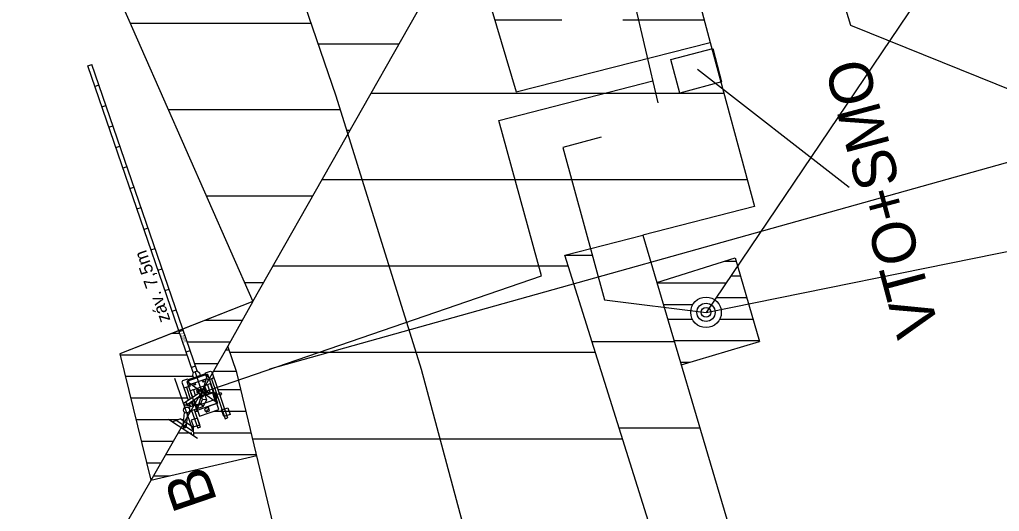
# Model space of a CAD drawing. Extents: x -553916 to -552953, y -1067470 to -1066637.
# Drawn here: x -553520.24 to -553497.58, y -1066994.91 to -1066983.52 of the extents above; entities that cross this region are included whole.
import ezdxf

# ---------------------------------------------------------------- set-up
doc = ezdxf.new("R2010")
doc.units = 0
for name, color, linetype in [('Hranice parcel', 7, 'Continuous'), ('Kolej', 7, 'Continuous'), ('Nová kabelizace', 7, 'Continuous'), ('nové prvky ZZ', 7, 'Continuous'), ('Propustek', 7, 'Continuous'), ('trasa_NN_popisky', 7, 'Continuous'), ('trasa_NN_uzemneni', 7, 'Continuous'), ('Vrstva 1', 7, 'Continuous'), ('Vrstva 28', 7, 'Continuous'), ('Vrstva 58', 7, 'Continuous')]:
    doc.layers.add(name, color=color, linetype=linetype)

msp = doc.modelspace()

# ---------------------------------------------------------------- linework, layer by layer
at = {"layer": 'Hranice parcel'}
for points in [[(-553481.25, -1066991.64), (-553501.02, -1066983.66), (-553503.13, -1066976.7), (-553485.37, -1066948.09)], [(-553515.43, -1066991.08), (-553526.38, -1067010.19), (-553539.65, -1067043.59), (-553548.33, -1067069.03)]]:
    msp.add_lwpolyline(points, dxfattribs=at)
at = {"layer": 'Kolej'}
msp.add_lwpolyline([(-553503.324, -1067065.808), (-553502.678, -1067054.027), (-553502.762, -1067041.504), (-553503.626, -1067029.057), (-553504.756, -1067019.974), (-553506.183, -1067011.388), (-553508.328, -1067001.388), (-553510.948, -1066991.622), (-553512.921, -1066985.291), (-553515.647, -1066977.347), (-553517.422, -1066972.53), (-553519.157, -1066967.95), (-553522.886, -1066958.375), (-553529.101, -1066942.549), (-553538.686, -1066918.107), (-553542.908, -1066907.329), (-553546.692, -1066897.676), (-553555.025, -1066876.441), (-553564.644, -1066851.894), (-553574.241, -1066827.427), (-553583.19, -1066804.618)], dxfattribs=at)
at = {"layer": 'Nová kabelizace'}
for p, q in [((-553505.478, -1066985.448), (-553507.017, -1066978.813)), ((-553509.157, -1066985.86), (-553505.596, -1066984.938)), ((-553508.173, -1066989.45), (-553509.157, -1066985.86)), ((-553516.02, -1066992.15), (-553508.173, -1066989.45))]:
    msp.add_line(p, q, dxfattribs=at)
at = {"layer": 'nové prvky ZZ'}
for p, q in [((-553505.18, -1066984.448), (-553504.213, -1066984.191)), ((-553504.213, -1066984.191), (-553504.008, -1066984.964)), ((-553518.666, -1066984.593), (-553518.572, -1066984.56)), ((-553516.232, -1066991.687), (-553518.666, -1066984.593)), ((-553516.138, -1066991.654), (-553518.572, -1066984.56)), ((-553504.568, -1066984.671), (-553501.059, -1066987.4)), ((-553518.504, -1066985.066), (-553518.41, -1066985.033)), ((-553518.341, -1066985.538), (-553518.248, -1066985.506)), ((-553518.179, -1066986.011), (-553518.085, -1066985.979)), ((-553518.017, -1066986.484), (-553517.923, -1066986.452)), ((-553517.855, -1066986.957), (-553517.761, -1066986.925)), ((-553517.692, -1066987.43), (-553517.598, -1066987.398)), ((-553517.53, -1066987.903), (-553517.436, -1066987.871)), ((-553517.368, -1066988.376), (-553517.274, -1066988.344)), ((-553517.205, -1066988.849), (-553517.112, -1066988.817)), ((-553517.043, -1066989.322), (-553516.949, -1066989.29)), ((-553516.881, -1066989.795), (-553516.787, -1066989.763)), ((-553516.719, -1066990.268), (-553516.625, -1066990.236)), ((-553516.556, -1066990.741), (-553516.462, -1066990.708)), ((-553516.394, -1066991.214), (-553516.3, -1066991.181)), ((-553516.176, -1066991.542), (-553516.27, -1066991.574)), ((-553516.232, -1066991.687), (-553516.138, -1066991.654)), ((-553516.02, -1066992.15), (-553516.185, -1066991.67)), ((-553515.946, -1066991.701), (-553515.827, -1066991.66)), ((-553515.827, -1066991.66), (-553515.798, -1066991.673)), ((-553515.798, -1066991.673), (-553515.432, -1066992.74)), ((-553516.241, -1066993.022), (-553516.65, -1066991.83)), ((-553516.476, -1066991.883), (-553516.491, -1066991.911)), ((-553516.491, -1066991.911), (-553516.348, -1066992.329)), ((-553516.357, -1066991.842), (-553516.476, -1066991.883)), ((-553515.895, -1066991.731), (-553516.377, -1066991.897)), ((-553516.377, -1066991.897), (-553516.145, -1066992.568)), ((-553515.664, -1066992.402), (-553516.377, -1066991.897)), ((-553516.352, -1066991.858), (-553516.357, -1066991.842)), ((-553516.222, -1066991.814), (-553516.065, -1066991.76)), ((-553515.895, -1066991.731), (-553516.145, -1066992.568)), ((-553515.941, -1066991.717), (-553515.946, -1066991.701)), ((-553515.902, -1066991.829), (-553515.891, -1066991.862)), ((-553515.895, -1066991.731), (-553515.664, -1066992.402)), ((-553515.891, -1066991.862), (-553515.772, -1066991.822)), ((-553515.806, -1066991.833), (-553515.488, -1066992.759)), ((-553515.772, -1066991.822), (-553515.757, -1066991.793)), ((-553516.421, -1066992.044), (-553516.45, -1066992.031)), ((-553516.302, -1066992.003), (-553516.421, -1066992.044)), ((-553516.387, -1066992.033), (-553516.297, -1066992.295)), ((-553516.313, -1066991.97), (-553516.302, -1066992.003)), ((-553516.3, -1066992.111), (-553516.23, -1066992.087)), ((-553516.3, -1066992.111), (-553516.248, -1066992.262)), ((-553516.23, -1066992.087), (-553516.228, -1066992.091)), ((-553516.228, -1066992.091), (-553516.224, -1066992.09)), ((-553515.899, -1066991.978), (-553516.224, -1066992.09)), ((-553516.224, -1066992.09), (-553516.18, -1066992.216)), ((-553516.106, -1066992.104), (-553516.125, -1066992.116)), ((-553516.125, -1066992.116), (-553516.111, -1066992.136)), ((-553516.106, -1066992.166), (-553516.113, -1066992.146)), ((-553516.111, -1066992.136), (-553516.093, -1066992.124)), ((-553516.096, -1066992.159), (-553516.102, -1066992.142)), ((-553516.06, -1066992.081), (-553516.095, -1066992.103)), ((-553516.077, -1066992.105), (-553516.089, -1066992.113)), ((-553516.025, -1066992.152), (-553516.015, -1066992.148)), ((-553516.022, -1066992.145), (-553516.019, -1066992.155)), ((-553515.928, -1066992.156), (-553515.951, -1066992.09)), ((-553515.918, -1066992.148), (-553515.939, -1066992.087)), ((-553515.897, -1066992.14), (-553515.93, -1066992.151)), ((-553515.894, -1066991.977), (-553515.899, -1066991.978)), ((-553515.899, -1066991.978), (-553515.833, -1066992.169)), ((-553515.888, -1066992.141), (-553515.897, -1066992.14)), ((-553515.826, -1066991.948), (-553515.895, -1066991.972)), ((-553515.895, -1066991.972), (-553515.894, -1066991.977)), ((-553515.878, -1066992.146), (-553515.888, -1066992.141)), ((-553515.872, -1066992.153), (-553515.878, -1066992.146)), ((-553515.748, -1066992.173), (-553515.826, -1066991.948)), ((-553516.433, -1066992.387), (-553516.092, -1066992.157)), ((-553516.393, -1066992.443), (-553516.052, -1066992.215)), ((-553516.274, -1066992.363), (-553516.238, -1066992.467)), ((-553516.212, -1066992.323), (-553516.218, -1066992.334)), ((-553516.183, -1066992.409), (-553516.212, -1066992.322)), ((-553516.16, -1066992.44), (-553516.203, -1066992.316)), ((-553516.034, -1066992.25), (-553516.178, -1066992.299)), ((-553516.039, -1066992.24), (-553516.142, -1066992.275)), ((-553516.056, -1066992.404), (-553516.013, -1066992.312)), ((-553516.038, -1066992.237), (-553516.045, -1066992.218)), ((-553516.04, -1066992.238), (-553516.024, -1066992.227)), ((-553516.027, -1066992.259), (-553516.04, -1066992.238)), ((-553516.013, -1066992.312), (-553516.035, -1066992.245)), ((-553516.01, -1066992.247), (-553516.027, -1066992.259)), ((-553515.917, -1066992.32), (-553516.013, -1066992.312)), ((-553516.001, -1066992.22), (-553516.012, -1066992.228)), ((-553515.97, -1066992.211), (-553516.006, -1066992.237)), ((-553515.995, -1066992.476), (-553515.917, -1066992.32)), ((-553515.917, -1066992.32), (-553515.958, -1066992.2)), ((-553515.792, -1066992.155), (-553515.954, -1066992.211)), ((-553515.789, -1066992.166), (-553515.951, -1066992.221)), ((-553515.894, -1066992.151), (-553515.92, -1066992.16)), ((-553515.885, -1066992.151), (-553515.894, -1066992.151)), ((-553515.874, -1066992.183), (-553515.885, -1066992.151)), ((-553515.863, -1066992.179), (-553515.872, -1066992.153)), ((-553515.774, -1066992.155), (-553515.792, -1066992.155)), ((-553515.777, -1066992.17), (-553515.789, -1066992.166)), ((-553515.726, -1066992.317), (-553515.777, -1066992.17)), ((-553515.763, -1066992.169), (-553515.774, -1066992.155)), ((-553515.713, -1066992.312), (-553515.763, -1066992.169)), ((-553515.69, -1066992.251), (-553515.712, -1066992.189)), ((-553515.682, -1066992.193), (-553515.645, -1066992.18)), ((-553515.645, -1066992.18), (-553515.636, -1066992.18)), ((-553515.636, -1066992.18), (-553515.622, -1066992.185)), ((-553515.586, -1066992.162), (-553515.597, -1066992.166)), ((-553515.584, -1066992.167), (-553515.586, -1066992.162)), ((-553515.574, -1066992.195), (-553515.586, -1066992.199)), ((-553515.577, -1066992.164), (-553515.584, -1066992.167)), ((-553515.569, -1066992.188), (-553515.577, -1066992.164)), ((-553515.569, -1066992.188), (-553515.576, -1066992.191)), ((-553515.576, -1066992.191), (-553515.574, -1066992.195)), ((-553516.364, -1066992.434), (-553516.357, -1066992.432)), ((-553516.356, -1066992.458), (-553516.364, -1066992.434)), ((-553516.359, -1066992.428), (-553516.347, -1066992.424)), ((-553516.357, -1066992.432), (-553516.359, -1066992.428)), ((-553516.356, -1066992.458), (-553516.349, -1066992.456)), ((-553516.349, -1066992.456), (-553516.347, -1066992.46)), ((-553516.347, -1066992.46), (-553516.336, -1066992.456)), ((-553516.056, -1066992.404), (-553516.342, -1066992.502)), ((-553516.324, -1066992.397), (-553516.294, -1066992.486)), ((-553516.316, -1066992.586), (-553515.995, -1066992.476)), ((-553516.308, -1066992.41), (-553516.315, -1066992.423)), ((-553516.301, -1066992.405), (-553516.308, -1066992.41)), ((-553516.264, -1066992.392), (-553516.301, -1066992.405)), ((-553516.265, -1066992.569), (-553516.125, -1066992.978)), ((-553516.21, -1066992.549), (-553516.069, -1066992.958)), ((-553515.663, -1066992.402), (-553516.145, -1066992.568)), ((-553515.72, -1066992.422), (-553516.145, -1066992.568)), ((-553515.995, -1066992.476), (-553516.056, -1066992.404)), ((-553515.86, -1066992.547), (-553515.857, -1066992.546)), ((-553516.132, -1066993.216), (-553516.803, -1066992.78)), ((-553516.719, -1066992.834), (-553516.533, -1066992.76)), ((-553516.22, -1066993.062), (-553516.626, -1066992.797)), ((-553516.223, -1066992.962), (-553516.533, -1066992.76)), ((-553516.464, -1066992.923), (-553516.429, -1066992.616)), ((-553516.385, -1066992.933), (-553516.349, -1066992.625)), ((-553515.488, -1066992.759), (-553515.432, -1066992.74)), ((-553516.467, -1066992.998), (-553516.378, -1066992.861)), ((-553516.414, -1066992.928), (-553516.431, -1066992.931)), ((-553516.424, -1066992.921), (-553516.422, -1066992.938)), ((-553516.216, -1066993.162), (-553516.223, -1066992.962)), ((-553516.069, -1066992.958), (-553516.125, -1066992.978))]:
    msp.add_line(p, q, dxfattribs=at)
for points in [[(-553504.008, -1066984.964), (-553504.974, -1066985.221), (-553505.18, -1066984.448)], [(-553516.232, -1066991.687), (-553516.244, -1066991.755), (-553516.223, -1066991.814)], [(-553516.138, -1066991.654), (-553516.086, -1066991.701), (-553516.066, -1066991.76)], [(-553516.004, -1066991.904), (-553516.008, -1066991.906), (-553516.021, -1066991.87), (-553515.993, -1066991.861), (-553515.981, -1066991.897), (-553515.986, -1066991.898)], [(-553515.986, -1066991.898), (-553515.983, -1066991.906), (-553516.001, -1066991.912), (-553516.004, -1066991.904)], [(-553516.202, -1066991.973), (-553516.207, -1066991.974), (-553516.22, -1066991.938), (-553516.192, -1066991.929), (-553516.179, -1066991.965), (-553516.184, -1066991.966)], [(-553516.184, -1066991.966), (-553516.182, -1066991.974), (-553516.2, -1066991.981), (-553516.202, -1066991.973)], [(-553516.109, -1066992.095), (-553516.113, -1066992.085), (-553516.151, -1066992.099), (-553516.135, -1066992.144)], [(-553516.112, -1066992.135), (-553516.145, -1066992.147), (-553516.141, -1066992.156), (-553516.092, -1066992.139)], [(-553516.085, -1066992.118), (-553516.103, -1066992.091), (-553516.111, -1066992.096), (-553516.089, -1066992.128)], [(-553516.09, -1066992.128), (-553516.107, -1066992.134)], [(-553515.971, -1066992.087), (-553515.934, -1066992.075), (-553515.95, -1066992.03), (-553515.988, -1066992.043), (-553515.974, -1066992.086)], [(-553515.963, -1066992.095), (-553515.923, -1066992.081), (-553515.926, -1066992.072), (-553515.971, -1066992.087), (-553515.971, -1066992.088)], [(-553516.264, -1066992.357), (-553516.229, -1066992.458), (-553516.24, -1066992.462), (-553516.274, -1066992.363)], [(-553516.218, -1066992.432), (-553516.236, -1066992.438), (-553516.257, -1066992.376), (-553516.24, -1066992.37)], [(-553516.24, -1066992.37), (-553516.248, -1066992.346)], [(-553516.244, -1066992.343), (-553516.217, -1066992.334), (-553516.191, -1066992.412)], [(-553516.016, -1066992.222), (-553515.998, -1066992.25), (-553516.005, -1066992.255), (-553516.027, -1066992.222)], [(-553515.943, -1066992.168), (-553515.942, -1066992.171), (-553515.916, -1066992.162), (-553515.919, -1066992.153), (-553515.942, -1066992.161)], [(-553515.712, -1066992.189), (-553515.72, -1066992.164), (-553515.753, -1066992.175), (-553515.726, -1066992.252)], [(-553515.69, -1066992.251), (-553515.678, -1066992.247), (-553515.7, -1066992.185), (-553515.712, -1066992.189)], [(-553515.704, -1066992.285), (-553515.682, -1066992.277), (-553515.69, -1066992.251)], [(-553515.617, -1066992.169), (-553515.621, -1066992.157), (-553515.631, -1066992.161), (-553515.609, -1066992.224), (-553515.6, -1066992.221), (-553515.603, -1066992.209)], [(-553515.597, -1066992.166), (-553515.599, -1066992.162), (-553515.617, -1066992.169)], [(-553515.603, -1066992.209), (-553515.585, -1066992.203), (-553515.586, -1066992.199)], [(-553516.347, -1066992.424), (-553516.348, -1066992.419), (-553516.33, -1066992.413)], [(-553516.316, -1066992.454), (-553516.334, -1066992.46), (-553516.336, -1066992.456)], [(-553516.33, -1066992.413), (-553516.333, -1066992.403)], [(-553516.329, -1066992.4), (-553516.324, -1066992.399), (-553516.302, -1066992.462), (-553516.312, -1066992.465), (-553516.316, -1066992.454)], [(-553516.21, -1066992.457), (-553516.218, -1066992.432)], [(-553516.187, -1066992.449), (-553516.199, -1066992.414), (-553516.183, -1066992.409), (-553516.171, -1066992.444)], [(-553515.857, -1066992.546), (-553515.874, -1066992.498), (-553515.968, -1066992.53), (-553515.949, -1066992.584), (-553515.909, -1066992.57)], [(-553515.905, -1066992.583), (-553515.932, -1066992.592), (-553515.928, -1066992.604), (-553515.901, -1066992.594)], [(-553515.901, -1066992.594), (-553515.849, -1066992.577), (-553515.86, -1066992.547), (-553515.911, -1066992.564), (-553515.905, -1066992.583)]]:
    msp.add_lwpolyline(points, dxfattribs=at)
for points in [[(-553515.902, -1066991.829), (-553515.941, -1066991.717), (-553516.352, -1066991.858), (-553516.313, -1066991.97)], [(-553516.121, -1066992.088), (-553516.126, -1066992.073), (-553516.148, -1066992.081), (-553516.143, -1066992.096)], [(-553515.958, -1066992.033), (-553515.963, -1066992.017), (-553515.985, -1066992.025), (-553515.98, -1066992.04)], [(-553515.634, -1066992.544), (-553515.713, -1066992.312), (-553516.163, -1066992.467), (-553516.083, -1066992.699)], [(-553515.922, -1066992.164), (-553515.919, -1066992.171), (-553515.936, -1066992.177), (-553515.939, -1066992.17)], [(-553515.7, -1066992.298), (-553515.717, -1066992.249), (-553515.733, -1066992.254), (-553515.716, -1066992.303)], [(-553515.658, -1066992.262), (-553515.694, -1066992.16), (-553515.707, -1066992.164), (-553515.672, -1066992.267)], [(-553515.521, -1066992.71), (-553515.574, -1066992.555), (-553515.428, -1066992.504), (-553515.375, -1066992.66)], [(-553516.073, -1066992.899), (-553516.126, -1066992.744), (-553516.273, -1066992.794), (-553516.219, -1066992.95)]]:
    msp.add_lwpolyline(points, close=True, dxfattribs=at)
for centre, radius in [((-553516.02, -1066992.15), 0.0725), ((-553516.383, -1066992.561), 0.0716), ((-553516.413, -1066992.415), 0.0347), ((-553516.423, -1066992.929), 0.00856)]:
    msp.add_circle(centre, radius, dxfattribs=at)
for centre, radius, start, end in [((-553516.02, -1066992.15), 0.0795, 309.387, 119.921), ((-553516.424, -1066992.927), 0.0399, 173.2567, 354.9637)]:
    msp.add_arc(centre, radius, start, end, dxfattribs=at)
at = {"layer": 'Propustek'}
for p, q in [((-553514.85, -1066990.05), (-553509.91, -1066981.33)), ((-553504.27, -1066984.05), (-553503.25, -1066987.85)), ((-553512.115, -1066985.222), (-553503.955, -1066985.222)), ((-553513.248, -1066987.222), (-553503.419, -1066987.222)), ((-553503.25, -1066987.85), (-553505.83, -1066988.51)), ((-553505.83, -1066988.51), (-553499.28, -1067010.65)), ((-553507.63, -1066988.97), (-553507, -1066988.97)), ((-553514.381, -1066989.222), (-553507.551, -1066989.222)), ((-553507.003, -1066990.97), (-553505.102, -1066990.97)), ((-553515.381, -1066991.222), (-553506.924, -1066991.222)), ((-553506.376, -1066992.97), (-553504.511, -1066992.97)), ((-553514.853, -1066993.222), (-553506.297, -1066993.222))]:
    msp.add_line(p, q, dxfattribs=at)
for points in [[(-553509.91, -1066981.33), (-553508.76, -1066985.19), (-553504.27, -1066984.05)], [(-553498.68, -1067074.42), (-553498.17, -1067040.43), (-553500.08, -1067020.73), (-553503.77, -1067001.28), (-553507.63, -1066988.97), (-553505.83, -1066988.51)], [(-553509.03, -1067072.35), (-553507.22, -1067040.68), (-553509.18, -1067016.9), (-553515.22, -1066991.69), (-553515.43, -1066991.08)]]:
    msp.add_lwpolyline(points, dxfattribs=at)
at = {"layer": 'trasa_NN_popisky'}
msp.add_lwpolyline([(-553456.479, -1066963.507), (-553494.623, -1066975.849), (-553504.368, -1066990.297)], dxfattribs=at)
at = {"layer": 'trasa_NN_uzemneni'}
msp.add_lwpolyline([(-553506.79, -1066986.24), (-553507.681, -1066986.481), (-553506.717, -1066990.005), (-553504.368, -1066990.297)], dxfattribs=at)
for radius in [0.354, 0.211, 0.111]:
    msp.add_circle((-553504.368, -1066990.297), radius, dxfattribs=at)
at = {"layer": 'Vrstva 1'}
for p, q in [((-553506.23, -1066976.75), (-553504.27, -1066984.05)), ((-553519.4, -1066979.7), (-553514.85, -1066990.05)), ((-553505.506, -1066989.604), (-553503.69, -1066989.038)), ((-553503.93, -1066989.113), (-553503.669, -1066989.113)), ((-553503.69, -1066989.038), (-553503.132, -1066990.969)), ((-553505.504, -1066989.613), (-553503.906, -1066989.613)), ((-553503.798, -1066989.452), (-553503.571, -1066989.452)), ((-553514.85, -1066990.05), (-553517.928, -1066991.256)), ((-553514.85, -1066990.05), (-553516.997, -1066990.892)), ((-553514.85, -1066990.05), (-553515.43, -1066991.08)), ((-553504.135, -1066989.952), (-553503.426, -1066989.952)), ((-553505.356, -1066990.113), (-553504.67, -1066990.113)), ((-553515.951, -1066990.482), (-553515.093, -1066990.482)), ((-553505.255, -1066990.452), (-553504.685, -1066990.452)), ((-553504.05, -1066990.452), (-553503.282, -1066990.452)), ((-553516.706, -1066990.778), (-553516.543, -1066990.778)), ((-553516.997, -1066990.892), (-553517.928, -1066991.256)), ((-553516.368, -1066990.982), (-553515.375, -1066990.982)), ((-553505.108, -1066990.952), (-553503.137, -1066990.952)), ((-553504.941, -1066991.514), (-553503.132, -1066990.969)), ((-553515.477, -1066991.162), (-553515.402, -1066991.162)), ((-553517.928, -1066991.256), (-553517.209, -1066994.185)), ((-553517.923, -1066991.278), (-553516.372, -1066991.278)), ((-553504.96, -1066991.452), (-553504.735, -1066991.452)), ((-553516.197, -1066991.482), (-553515.66, -1066991.482)), ((-553515.763, -1066991.662), (-553515.23, -1066991.662)), ((-553517.8, -1066991.778), (-553516.236, -1066991.778)), ((-553515.657, -1066992.084), (-553515.126, -1066992.084)), ((-553517.677, -1066992.278), (-553516.365, -1066992.278)), ((-553516.292, -1066992.584), (-553516.26, -1066992.584)), ((-553516.198, -1066992.584), (-553516.123, -1066992.584)), ((-553515.749, -1066992.584), (-553515.564, -1066992.584)), ((-553515.657, -1066992.584), (-553515.126, -1066992.584)), ((-553515.401, -1066992.584), (-553515.006, -1066992.584)), ((-553517.554, -1066992.778), (-553516.578, -1066992.778)), ((-553516.506, -1066992.778), (-553516.447, -1066992.778)), ((-553517.432, -1066993.278), (-553516.689, -1066993.278)), ((-553516.578, -1066993.084), (-553516.335, -1066993.084)), ((-553516.292, -1066993.084), (-553516.26, -1066993.084)), ((-553516.219, -1066993.084), (-553514.886, -1066993.084)), ((-553516.198, -1066993.084), (-553516.123, -1066993.084)), ((-553515.749, -1066993.084), (-553515.564, -1066993.084)), ((-553515.401, -1066993.084), (-553515.006, -1066993.084)), ((-553517.209, -1066994.185), (-553514.76, -1066993.609)), ((-553516.865, -1066993.584), (-553515.804, -1066993.584)), ((-553516.578, -1066993.584), (-553516.335, -1066993.584)), ((-553516.219, -1066993.584), (-553514.766, -1066993.584)), ((-553517.309, -1066993.778), (-553516.976, -1066993.778)), ((-553517.151, -1066994.084), (-553516.781, -1066994.084))]:
    msp.add_line(p, q, dxfattribs=at)
at = {"layer": 'Vrstva 28'}
for p, q in [((-553261.015, -1066920.514), (-553514.461, -1066991.614)), ((-553504.368, -1066990.297), (-553260.214, -1066940.912))]:
    msp.add_line(p, q, dxfattribs=at)
at = {"layer": 'Vrstva 58'}
for p, q in [((-553509.255, -1066983.528), (-553507.702, -1066983.528)), ((-553506.294, -1066983.528), (-553504.41, -1066983.528)), ((-553517.684, -1066983.603), (-553513.5, -1066983.603)), ((-553513.336, -1066984.081), (-553511.468, -1066984.081)), ((-553516.805, -1066985.603), (-553512.824, -1066985.603)), ((-553512.675, -1066986.081), (-553512.602, -1066986.081)), ((-553515.926, -1066987.603), (-553513.464, -1066987.603)), ((-553515.047, -1066989.603), (-553514.597, -1066989.603))]:
    msp.add_line(p, q, dxfattribs=at)

# ---------------------------------------------------------------- texts
at = {"layer": 'nové prvky ZZ'}
for s, height, rotation, p in [('VTO+SMO', 1, 104.9376, (-553498.965, -1066990.707)), ('záv. 7,5m', 0.3, 109.138, (-553516.752, -1066990.475)), ('7,50m', 0.0646, 288.9398, (-553516.526, -1066990.764)), ('265', 0.025, 288.9398, (-553515.996, -1066992.119)), ('B', 1.025, 108.8917, (-553515.663, -1066994.668))]:
    msp.add_text(s, height=height, rotation=rotation, dxfattribs=at).set_placement(p)

doc.saveas('drawing.dxf')
